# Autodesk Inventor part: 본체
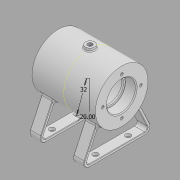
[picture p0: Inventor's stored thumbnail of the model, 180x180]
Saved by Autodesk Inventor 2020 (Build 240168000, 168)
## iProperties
Created: 2021-12
Part Number: 본체
Material: 일반
Document SubType Name: Modeling
Designer: MIRAE
Density: 1 g/cm^3
Appearance: 기본값
Author: MIRAE
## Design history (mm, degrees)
sketch "스케치1"
  geometry: L1 (0, 0)-(70, 0); L2 (70, 0)-(70, 29); L3 (70, 29)-(0, 29); L4 (0, 29)-(0, 0); L5 (0, 16)-(12, 16); L6 (12, 16)-(12, 14); L7 (12, 14)-(14, 14); L8 (14, 14)-(14, 21); L9 (14, 21)-(56, 21); L10 (56, 21)-(56, 14); L11 (56, 14)-(58, 14); L12 (58, 14)-(58, 16); L13 (58, 16)-(70, 16)
  constraints: 26 end point, 7 perpendicular, 5 point on line, 3 horizontal, 2 parallel
  dimensions: "d0" = 58 diameter of L3 L1; "d1" = 70 distance of L2.end L3.end; "d5" = 32 diameter of L13 L1; "d6" = 28 diameter of L11 L1; "d7" = 42 diameter of L9 L1; "d8" = 12 distance of L12.end L13.end; "d9" = 42 distance of L8.end L9.end; "d10" = 2 distance of L10.end L11.end; "d11" = 2 distance of L6.end L7.end
revolve "회전1" sketch "스케치1" stored, may be unused: angle "d12" = 90 deg
node "작업 평면1"
sketch "스케치2"
  geometry: L1 (0, -55)-(40, -55); L2 (40, -55)-(22.743, -17.993); L3 (0, -52)-(35.291, -52); L4 (35.291, -52)-(20.574, -20.438); L5 (0, -29)-(0, -62.069); L6 (-40, -55)-(-22.743, -17.993); L7 (-35.291, -52)-(-20.574, -20.438); L8 (0, -52)-(-35.291, -52); L9 (0, -55)-(-40, -55); C1 r 16 at (0, 0) reference; A1 r 29 centre (0, 0) between (-22.743, -17.993) and (22.743, -17.993) reference; A2 r 29 centre (0, 0) between (-22.743, -17.993) and (22.743, -17.993); A3 r 29 centre (0, 0) between (-22.743, -17.993) and (22.743, -17.993); 9 further points
  constraints: 18 end point, 9 point on circle, 9 point on line, 4 symmetric about line, 2 centre point, 2 concentric, 2 horizontal, 2 horizontal alignment, 1 parallel, 1 vertical
  dimensions: "d14" = 3 distance between parallel lines of L4 L2; "d15" = 3 distance between parallel lines of L1 L3; "d17" = 65 deg angle of L1 L2; "d19" = 55 distance from line of L1 point (0, 0); "d85" = 80 distance of point (40, -55) L6.start
extrude "돌출1" join sketch "스케치2" distance "d22" = 12; taper "d23" = 0 deg
node "작업 평면2"
sketch "스케치3" dims "d30" = 42
  geometry: 3 further points
  constraints: 2 vertical alignment, 1 coincident, 2 other
hole "구멍1" sketch "스케치3" at (0, 21) diameter "d31" = 3.242; stored, may be unused: countersink angle "d35" = 90 deg, drill point angle "d37" = 118 deg; dims "d32" = 8, "d33" = 4, "d34" = 2, "d36" = 10
sketch "스케치4"
  geometry: L1 (0, 0)-(0, 31.346); L2 (0, 0)-(10.945, -30.07); C1 r 29 at (0, 0) reference; C2 r 21 at (0, 0) reference; 1 further point
  constraints: 4 end point, 1 vertical
  dimensions: "d41" = 20 deg angle of L2 L1; "d42" = 32 distance of L1.start L2.end
  node "절단 모서리 투영2"
node "작업 평면4"
sketch "스케치5"
  geometry: C1 r 6 at (0, 0); 4 further points
  constraints: 1 centre point, 1 coincident
  dimensions: "d43" = 12 diameter of C1
extrude "돌출2" join sketch "스케치5" stored distance "d44" = 12; taper "d45" = 0 deg
sketch "스케치6"
  geometry: C1 r 6 at (0, 0) reference; 2 further points
  constraints: 1 coincident
hole "구멍2" sketch "스케치6" at (0, 0) diameter "d46" = 5.1881; stored, may be unused: countersink angle "d50" = 90 deg, drill point angle "d52" = 0 deg; dims "d47" = 12, "d48" = 4, "d49" = 2, "d51" = 16
node "작업 평면5"
sketch "스케치7"
  geometry: C1 r 5 at (-35, 0); 2 further points
  constraints: 1 centre point, 1 coincident
  dimensions: "d54" = 10 diameter of C1
extrude "돌출3" join sketch "스케치7" stored distance "d55" = 12; taper "d56" = 0 deg
sketch "스케치8"
  geometry: C1 r 5 at (0, 0) reference; 2 further points
  constraints: 1 coincident
hole "구멍3" sketch "스케치8" at (0, 0) diameter "d57" = 5.1881; stored, may be unused: countersink angle "d61" = 90 deg, drill point angle "d63" = 118 deg; dims "d58" = 6, "d59" = 4, "d60" = 2, "d62" = 8
sketch "스케치9"
  geometry: C1 r 5 at (0, 0) reference; 2 further points
  constraints: 1 coincident
hole "구멍4" sketch "스케치9" at (0, 0) diameter "d64" = 3; stored, may be unused: countersink angle "d68" = 90 deg, drill point angle "d70" = 118 deg; dims "d65" = 6, "d66" = 4, "d67" = 2, "d69" = 8
fillet "모깎기1" dims "d71" = 3
fillet "모깎기2" dims "d72" = 0.3
chamfer "모따기1" distance "d73" = 1; stored, may be unused: second distance "d74" = 2, angle "d75" = 45 deg
fillet "모깎기3" dims "d84" = 1
fillet "모깎기4" dims "d86" = 6
fillet "모깎기5" dims "d87" = 3
sketch "스케치11"
  geometry: L1 (60, -5.196)-(48, -5.196) reference; L2 (48, -5.196)-(48, 0) reference; L3 (48, 0)-(60, 0) reference; L4 (60, 61.164)-(60, 0) reference; L5 (48, 61.164)-(60, 61.164) reference; L6 (48, 61.164)-(48, 66.36) reference; L7 (48, 66.36)-(60, 66.36) reference; L8 (60, 66.36)-(60, 61.164) reference; L9 (60, 0)-(60, -5.196) reference; L10 (48, 0)-(48, 61.164) reference; L11 (12, -5.196)-(0, -5.196) reference; L12 (0, -5.196)-(0, 0) reference; L13 (12, 0)-(0, 0) reference; L14 (12, 61.164)-(12, 0) reference; L15 (12, 61.164)-(0, 61.164) reference; L16 (0, 61.164)-(0, 66.36) reference; L17 (0, 66.36)-(12, 66.36) reference; L18 (12, 66.36)-(12, 61.164) reference; L19 (12, 0)-(12, -5.196) reference; L20 (0, 0)-(0, 61.164) reference; L21 (60, 30.582)-(20.011, 30.582); 6 further points
  constraints: 2 end point, 2 midpoint, 2 vertical alignment, 1 horizontal, 1 horizontal alignment, 1 symmetric about line
  dimensions: "d96" = 48 distance of point (6, 12.582) point (54, 12.582); "d97" = 36 distance of point (6, 48.582) point (6, 12.582); "d98" = 48 distance of point (6, 48.582) point (54, 48.582)
hole "구멍7" sketch "스케치11" at (6, 48.582), (6, 12.582), (54, 48.582), (54, 12.582) diameter "d99" = 6; stored, may be unused: countersink angle "d103" = 90 deg, drill point angle "d105" = 118 deg; dims "d100" = 6, "d101" = 4, "d102" = 2, "d104" = 8
fillet "모깎기6" dims "d106" = 0.5
fillet "모깎기7" dims "d107" = 3
fillet "모깎기8" dims "d108" = 1
node "작업 평면6"
sketch "스케치12"
  geometry: L1 (-20.739, 3.002)-(20.739, 3.002); L2 (20.739, 3.002)-(20.739, -3.002); L3 (20.739, -3.002)-(-20.739, -3.002); L4 (-20.739, -3.002)-(-20.739, 3.002); L5 (-20.739, 3.002)-(20.739, -3.002); L6 (-35, 29)-(-35, -29) reference; 2 further points
  constraints: 2 end point, 1 midpoint, 2 other
  dimensions: "d109" = 35 distance from line of point (0, 0) L6; "d110" = 29 vertical distance of L6.start point (0, 0)
feature "엠보싱1" sketch "스케치12" dims "d0" = 58, "d1" = 70, "d5" = 32, "d6" = 28, "d7" = 42, "d8" = 12, "d9" = 42, "d10" = 2, "d11" = 2, "d14" = 3, "d15" = 3, "d17" = 65 deg, "d19" = 55, "d85" = 80, "d111" = 0.5, "d112" = 0
node "솔리드1"
mirror "미러1"
pattern_circular "원형 패턴1" dims angle "d39" = 360 deg
mirror "미러2"
node "작업 평면3"
node "절단 모서리 투영1"
node "절단 모서리 투영4"
feature "A9D066F2-1C7D-4E18-AEED-F7BC21143FA4" dims "d99" = 6, "d100" = 6, "d101" = 4, "d102" = 2, "d103" = 90 deg, "d104" = 8, "d105" = 118 deg
other parameters: "d13" = -5, "d53" = 32
